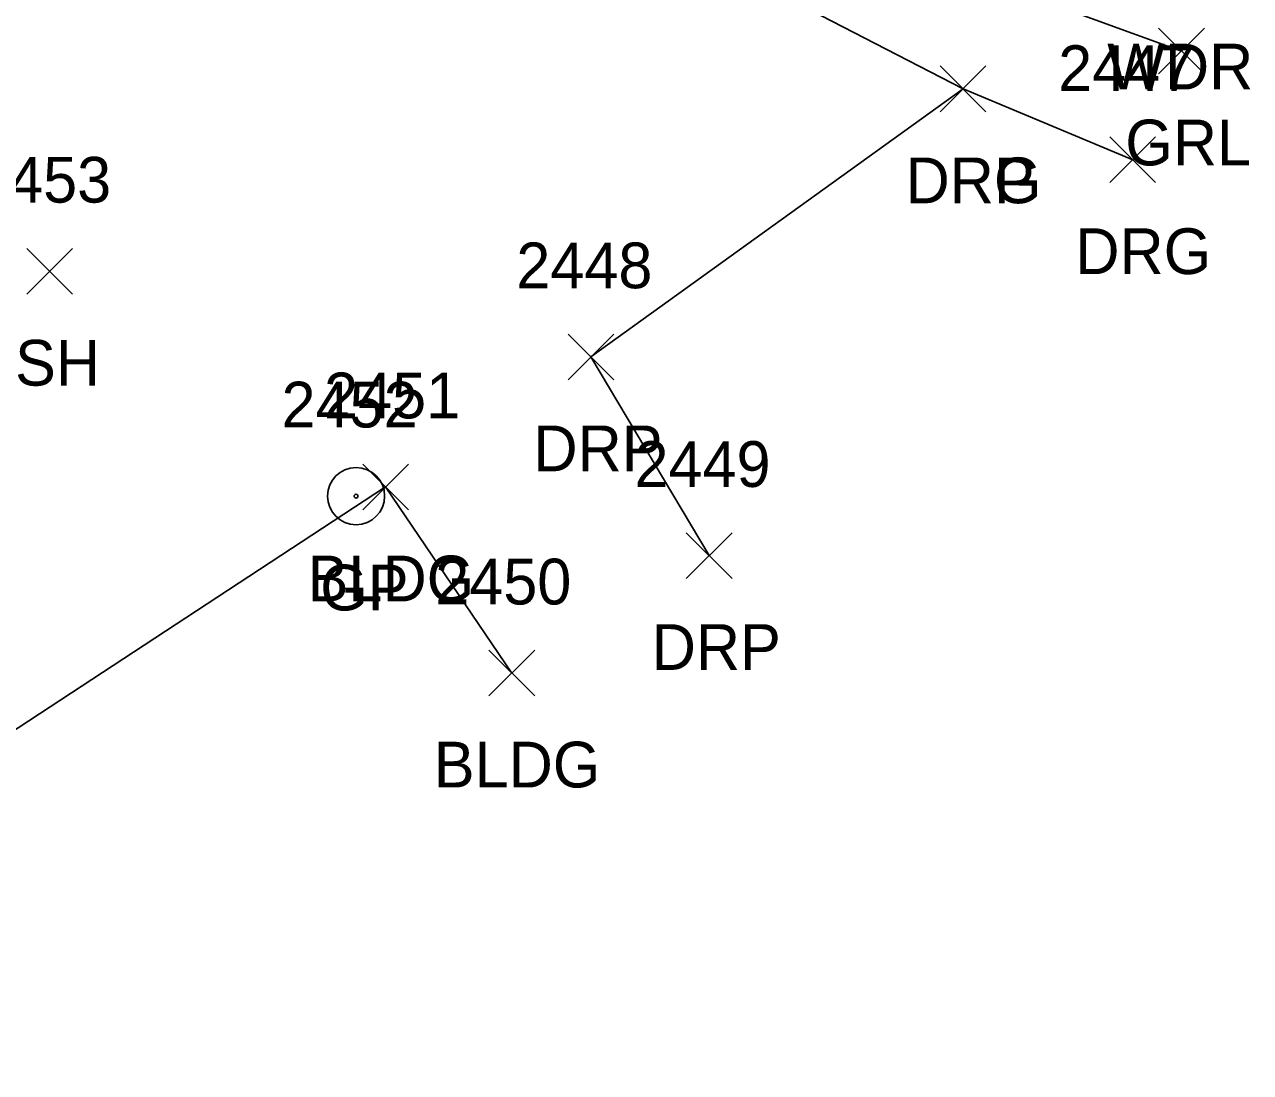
# Model space of a CAD drawing. Extents: x 1653135 to 1655489, y 602711 to 605684.
# Drawn here: x 1653800.2 to 1653853.8, y 605152 to 605197.8 of the extents above; entities that cross this region are included whole.
import ezdxf

# ---------------------------------------------------------------- set-up
doc = ezdxf.new("R2010")
doc.units = 0
for name, color, linetype in [('L_A', 7, 'Continuous'), ('L_I', 7, 'Continuous'), ('L_TIC', 7, 'Continuous'), ('LBC', 7, 'Continuous'), ('R_A', 7, 'Continuous'), ('R_I', 7, 'Continuous'), ('R_TIC', 7, 'Continuous'), ('RDG', 7, 'Continuous'), ('RDP', 7, 'Continuous'), ('RGP', 7, 'Continuous'), ('RGR', 7, 'Continuous')]:
    doc.layers.add(name, color=color, linetype=linetype)

msp = doc.modelspace()

# ---------------------------------------------------------------- linework, layer by layer
at = {"layer": 'L_TIC'}
for points in [[(1653800.312, 605185.986), (1653802.312, 605187.986)], [(1653802.312, 605185.986), (1653800.312, 605187.986)], [(1653800.312, 605185.986), (1653802.312, 605187.986)], [(1653802.312, 605185.986), (1653800.312, 605187.986)], [(1653815.001, 605176.555), (1653817.001, 605178.555)], [(1653817.001, 605176.555), (1653815.001, 605178.555)], [(1653815.001, 605176.555), (1653817.001, 605178.555)], [(1653817.001, 605176.555), (1653815.001, 605178.555)], [(1653820.515, 605168.42), (1653822.515, 605170.42)], [(1653822.515, 605168.42), (1653820.515, 605170.42)], [(1653820.515, 605168.42), (1653822.515, 605170.42)], [(1653822.515, 605168.42), (1653820.515, 605170.42)]]:
    msp.add_lwpolyline(points, dxfattribs=at)
at = {"layer": 'LBC'}
msp.add_lwpolyline([(1653821.515, 605169.42), (1653816.001, 605177.555), (1653793.518, 605162.828), (1653768.813, 605146.61), (1653771.902, 605142.216)], dxfattribs=at)
at = {"layer": 'R_TIC'}
for points in [[(1653849.789, 605195.613), (1653851.789, 605197.613)], [(1653851.789, 605195.613), (1653849.789, 605197.613)], [(1653849.789, 605195.613), (1653851.789, 605197.613)], [(1653851.789, 605195.613), (1653849.789, 605197.613)], [(1653840.24, 605193.958), (1653842.24, 605195.958)], [(1653842.24, 605193.958), (1653840.24, 605195.958)], [(1653840.24, 605193.958), (1653842.24, 605195.958)], [(1653842.24, 605193.958), (1653840.24, 605195.958)], [(1653840.24, 605193.958), (1653842.24, 605195.958)], [(1653842.24, 605193.958), (1653840.24, 605195.958)], [(1653840.24, 605193.958), (1653842.24, 605195.958)], [(1653842.24, 605193.958), (1653840.24, 605195.958)], [(1653847.661, 605190.862), (1653849.661, 605192.862)], [(1653849.661, 605190.862), (1653847.661, 605192.862)], [(1653847.661, 605190.862), (1653849.661, 605192.862)], [(1653849.661, 605190.862), (1653847.661, 605192.862)], [(1653823.972, 605182.242), (1653825.972, 605184.242)], [(1653825.972, 605182.242), (1653823.972, 605184.242)], [(1653823.972, 605182.242), (1653825.972, 605184.242)], [(1653825.972, 605182.242), (1653823.972, 605184.242)], [(1653829.144, 605173.558), (1653831.144, 605175.558)], [(1653831.144, 605173.558), (1653829.144, 605175.558)], [(1653829.144, 605173.558), (1653831.144, 605175.558)], [(1653831.144, 605173.558), (1653829.144, 605175.558)]]:
    msp.add_lwpolyline(points, dxfattribs=at)
at = {"layer": 'RDG'}
msp.add_lwpolyline([(1653841.24, 605194.958), (1653848.661, 605191.862)], dxfattribs=at)
at = {"layer": 'RDP'}
msp.add_lwpolyline([(1653765.921, 605244.563), (1653766.574, 605243.092), (1653769.345, 605238.77), (1653771.429, 605237.09), (1653783.763, 605232.898), (1653797.722, 605223.414), (1653814.893, 605208.556), (1653841.24, 605194.958), (1653824.972, 605183.242), (1653830.144, 605174.558)], dxfattribs=at)
at = {"layer": 'RGP'}
msp.add_line((1653814.707, 605177.157), (1653814.707, 605177.157), dxfattribs=at)
for radius in [1.25, 0.0833]:
    msp.add_circle((1653814.707, 605177.157), radius, dxfattribs=at)
at = {"layer": 'RGR'}
msp.add_lwpolyline([(1653804.704, 605221.986), (1653822.765, 605206.79), (1653850.789, 605196.613)], dxfattribs=at)

# ---------------------------------------------------------------- texts
at = {"layer": 'L_A'}
for s, p in [('WDR', (1653847.543, 605194.933)), ('WDR', (1653847.543, 605194.933)), ('SH', (1653799.8, 605181.986)), ('SH', (1653799.8, 605181.986)), ('BLDG', (1653812.592, 605172.555)), ('BLDG', (1653812.592, 605172.555)), ('BLDG', (1653818.105, 605164.42)), ('BLDG', (1653818.105, 605164.42))]:
    msp.add_text(s, height=2, dxfattribs=at).set_placement(p)
at = {"layer": 'L_I'}
for s, p in [('2453', (1653798.052, 605189.986)), ('2453', (1653798.052, 605189.986)), ('2451', (1653813.308, 605180.555)), ('2451', (1653813.308, 605180.555)), ('2450', (1653818.168, 605172.42)), ('2450', (1653818.168, 605172.42))]:
    msp.add_text(s, height=2, dxfattribs=at).set_placement(p)
at = {"layer": 'R_A'}
for s, p in [('GRL', (1653848.333, 605191.613)), ('GRL', (1653848.333, 605191.613)), ('DRG', (1653838.728, 605189.958)), ('DRG', (1653838.728, 605189.958)), ('DRP', (1653838.728, 605189.958)), ('DRP', (1653838.728, 605189.958)), ('DRG', (1653846.149, 605186.862)), ('DRG', (1653846.149, 605186.862)), ('DRP', (1653822.46, 605178.242)), ('DRP', (1653822.46, 605178.242)), ('GP', (1653813.14, 605172.157)), ('DRP', (1653827.632, 605169.558)), ('DRP', (1653827.632, 605169.558))]:
    msp.add_text(s, height=2, dxfattribs=at).set_placement(p)
at = {"layer": 'R_I'}
for s, p in [('2447', (1653845.401, 605194.862)), ('2447', (1653845.401, 605194.862)), ('2448', (1653821.712, 605186.242)), ('2448', (1653821.712, 605186.242)), ('2452', (1653811.448, 605180.157)), ('2449', (1653826.877, 605177.558)), ('2449', (1653826.877, 605177.558))]:
    msp.add_text(s, height=2, dxfattribs=at).set_placement(p)

doc.saveas('drawing.dxf')
